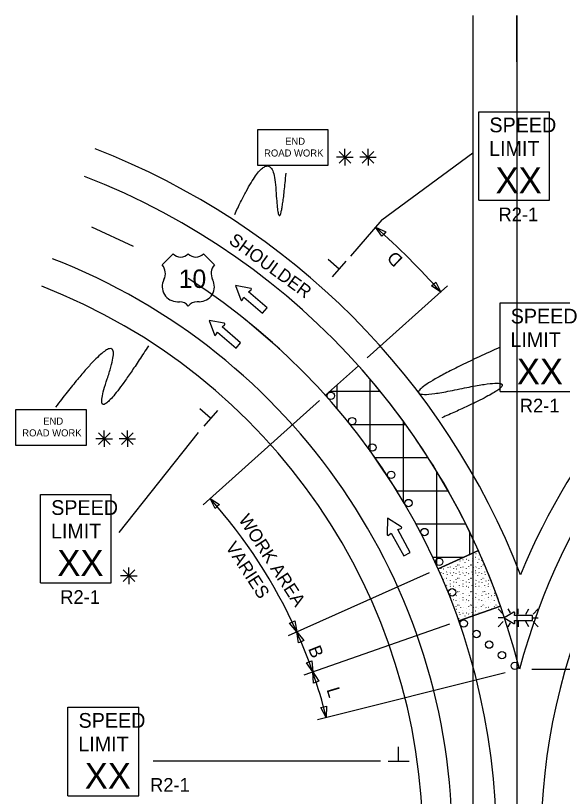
# Model space of a CAD drawing. Extents: x 16556 to 18479, y 5704 to 6974.
# Drawn here: x 16732.7 to 17029.3, y 6550.3 to 6974.1 of the extents above; entities that cross this region are included whole.
import ezdxf

# ---------------------------------------------------------------- set-up
doc = ezdxf.new("R2010")
doc.units = 0
for name, color, linetype in [('ALI_LEGAL_EX', 7, 'Continuous'), ('MT_SCRATCH_LEVEL_A', 7, 'Continuous'), ('MT_SCRATCH_LEVEL_E', 7, 'Continuous'), ('PAVT_EDGE_EX', 7, 'Continuous'), ('TRAFFIC_SIGNS_PR', 7, 'Continuous'), ('TYPICAL_EX', 7, 'Continuous'), ('TYPICAL_TEXT_DIMEN_PR', 7, 'Continuous')]:
    doc.layers.add(name, color=color, linetype=linetype)

msp = doc.modelspace()

# ---------------------------------------------------------------- linework, layer by layer
at = {"layer": 'ALI_LEGAL_EX'}
for p, q in [((16980.68, 6974.12), (16980.68, 6155.98)), ((17004.68, 6974.12), (17004.68, 6155.98)), ((16980.68, 6877.04), (16980.68, 6013.12)), ((17004.68, 6877.04), (17004.68, 6013.12))]:
    msp.add_line(p, q, dxfattribs=at)
for points in [[(17004.68, 6949.12), (17004.68, 6974.12)], [(16796.64, 6848.72), (16773.99, 6859.31)], [(16876.06, 6792.99), (16857.11, 6809.3)], [(16939.89, 6715.82), (16925.99, 6736.59)]]:
    msp.add_lwpolyline(points, dxfattribs=at)
for centre, radius, start, end in [((16629.65, 6525.15), 364, 0, 57.2958), ((17357.65, 6525.15), 340, 129.5666, 180)]:
    msp.add_arc(centre, radius, start, end, dxfattribs=at)
at = {"layer": 'MT_SCRATCH_LEVEL_A'}
for p, q in [((16918.68, 6784), (16900.8, 6767.99)), ((16918.68, 6784), (16900.8, 6767.99)), ((16907.15, 6760.43), (16907.15, 6773.68)), ((16925.15, 6737.43), (16925.15, 6776.33)), ((16903.28, 6770.2), (16930.27, 6770.2)), ((16943.15, 6709.93), (16943.15, 6753.45)), ((16914.07, 6752.2), (16944.07, 6752.2)), ((16927.54, 6734.2), (16956.3, 6734.2)), ((16961.15, 6675.37), (16961.15, 6726.68)), ((16939.35, 6716.2), (16967.15, 6716.2)), ((16949.72, 6698.2), (16976.74, 6698.2)), ((16979.15, 6681.58), (16979.15, 6693.23)), ((16958.82, 6680.2), (16976.08, 6680.2)), ((16983.8, 6683.65), (16961.89, 6673.85)), ((16961.89, 6673.85), (16983.8, 6683.65)), ((16983.8, 6683.65), (16961.89, 6673.85)), ((16978.69, 6681.1), (16978.74, 6681.02)), ((16980.98, 6681.91), (16981.03, 6681.84)), ((16982.43, 6682.06), (16982.48, 6682.18)), ((16984.05, 6681.24), (16984.1, 6681.16)), ((16969.7, 6677.27), (16969.74, 6677.37)), ((16972.49, 6676.04), (16972.54, 6675.96)), ((16973.22, 6676.01), (16973.28, 6675.93)), ((16973.63, 6678.11), (16973.69, 6678.03)), ((16975.41, 6678.78), (16975.47, 6678.89)), ((16976.59, 6677.27), (16976.64, 6677.39)), ((16977.21, 6679.03), (16977.26, 6678.95)), ((16978.49, 6678.45), (16978.5, 6678.33)), ((16979.38, 6676.04), (16979.43, 6675.96)), ((16980.11, 6676.01), (16980.16, 6675.93)), ((16980.33, 6679.31), (16980.38, 6679.42)), ((16980.52, 6678.11), (16980.57, 6678.03)), ((16982.26, 6680.18), (16982.31, 6680.1)), ((16982.3, 6678.78), (16982.35, 6678.89)), ((16983.48, 6677.27), (16983.53, 6677.39)), ((16984.1, 6679.03), (16984.15, 6678.95)), ((16985.38, 6678.45), (16985.39, 6678.33)), ((16986.26, 6676.04), (16986.31, 6675.96)), ((16987, 6676.01), (16987.05, 6675.93)), ((16963.39, 6673.95), (16963.44, 6673.87)), ((16963.44, 6671.74), (16963.49, 6671.66)), ((16964.84, 6675.08), (16964.89, 6675.19)), ((16964.92, 6673.81), (16964.97, 6673.73)), ((16966.56, 6672.02), (16966.61, 6672.14)), ((16967.21, 6674.63), (16967.26, 6674.55)), ((16968.48, 6672.89), (16968.53, 6672.81)), ((16968.65, 6674.78), (16968.71, 6674.9)), ((16970.27, 6673.95), (16970.33, 6673.87)), ((16970.32, 6671.74), (16970.37, 6671.66)), ((16971.72, 6675.08), (16971.78, 6675.19)), ((16971.8, 6673.81), (16971.85, 6673.73)), ((16973.44, 6672.02), (16973.5, 6672.14)), ((16974.09, 6674.63), (16974.15, 6674.55)), ((16975.37, 6672.89), (16975.42, 6672.81)), ((16975.54, 6674.78), (16975.59, 6674.9)), ((16977.16, 6673.95), (16977.21, 6673.87)), ((16977.21, 6671.74), (16977.26, 6671.66)), ((16978.61, 6675.08), (16978.66, 6675.19)), ((16978.69, 6673.81), (16978.74, 6673.73)), ((16980.33, 6672.02), (16980.38, 6672.14)), ((16980.98, 6674.63), (16981.03, 6674.55)), ((16982.26, 6672.89), (16982.31, 6672.81)), ((16982.43, 6674.78), (16982.48, 6674.9)), ((16984.05, 6673.95), (16984.1, 6673.87)), ((16984.1, 6671.74), (16984.15, 6671.66)), ((16985.5, 6675.08), (16985.55, 6675.19)), ((16985.58, 6673.81), (16985.63, 6673.73)), ((16987.22, 6672.02), (16987.27, 6672.14)), ((16964.72, 6671.17), (16964.73, 6671.05)), ((16964.84, 6667.79), (16964.89, 6667.91)), ((16965.6, 6668.75), (16965.65, 6668.68)), ((16966.34, 6668.72), (16966.39, 6668.65)), ((16966.75, 6670.82), (16966.8, 6670.74)), ((16968.53, 6671.49), (16968.58, 6671.61)), ((16968.65, 6667.49), (16968.71, 6667.61)), ((16969.7, 6669.99), (16969.76, 6670.11)), ((16971.6, 6671.17), (16971.62, 6671.05)), ((16971.72, 6667.79), (16971.78, 6667.91)), ((16972.49, 6668.75), (16972.54, 6668.68)), ((16973.22, 6668.72), (16973.28, 6668.65)), ((16973.63, 6670.82), (16973.69, 6670.74)), ((16975.41, 6671.49), (16975.47, 6671.61)), ((16975.54, 6667.49), (16975.59, 6667.61)), ((16976.59, 6669.99), (16976.64, 6670.11)), ((16978.49, 6671.17), (16978.5, 6671.05)), ((16978.61, 6667.79), (16978.66, 6667.91)), ((16979.38, 6668.75), (16979.43, 6668.68)), ((16980.11, 6668.72), (16980.16, 6668.65)), ((16980.52, 6670.82), (16980.57, 6670.74)), ((16982.3, 6671.49), (16982.35, 6671.61)), ((16982.43, 6667.49), (16982.48, 6667.61)), ((16983.48, 6669.99), (16983.53, 6670.11)), ((16985.38, 6671.17), (16985.39, 6671.05)), ((16985.5, 6667.79), (16985.55, 6667.91)), ((16986.26, 6668.75), (16986.31, 6668.68)), ((16987, 6668.72), (16987.05, 6668.65)), ((16987.41, 6670.82), (16987.46, 6670.74)), ((16989.32, 6667.49), (16989.37, 6667.61)), ((16966.56, 6664.74), (16966.61, 6664.85)), ((16966.75, 6663.54), (16966.8, 6663.46)), ((16967.21, 6667.34), (16967.26, 6667.27)), ((16968.48, 6665.61), (16968.53, 6665.53)), ((16968.53, 6664.21), (16968.58, 6664.32)), ((16970.27, 6666.67), (16970.33, 6666.59)), ((16970.32, 6664.46), (16970.37, 6664.38)), ((16971.6, 6663.88), (16971.62, 6663.76)), ((16971.8, 6666.53), (16971.85, 6666.45)), ((16973.44, 6664.74), (16973.5, 6664.85)), ((16973.63, 6663.54), (16973.69, 6663.46)), ((16974.09, 6667.34), (16974.15, 6667.27)), ((16975.37, 6665.61), (16975.42, 6665.53)), ((16975.41, 6664.21), (16975.47, 6664.32)), ((16977.16, 6666.67), (16977.21, 6666.59)), ((16977.21, 6664.46), (16977.26, 6664.38)), ((16978.49, 6663.88), (16978.5, 6663.76)), ((16978.69, 6666.53), (16978.74, 6666.45)), ((16980.33, 6664.74), (16980.38, 6664.85)), ((16980.52, 6663.54), (16980.57, 6663.46)), ((16980.98, 6667.34), (16981.03, 6667.27)), ((16982.26, 6665.61), (16982.31, 6665.53)), ((16982.3, 6664.21), (16982.35, 6664.32)), ((16984.05, 6666.67), (16984.1, 6666.59)), ((16984.1, 6664.46), (16984.15, 6664.38)), ((16985.38, 6663.88), (16985.39, 6663.76)), ((16985.58, 6666.53), (16985.63, 6666.45)), ((16987.22, 6664.74), (16987.27, 6664.85)), ((16987.41, 6663.54), (16987.46, 6663.46)), ((16987.87, 6667.34), (16987.92, 6667.27)), ((16989.15, 6665.61), (16989.2, 6665.53)), ((16989.19, 6664.21), (16989.24, 6664.32)), ((16990.99, 6664.46), (16991.04, 6664.38)), ((16968.65, 6660.21), (16968.71, 6660.33)), ((16969.7, 6662.7), (16969.76, 6662.82)), ((16970.27, 6659.38), (16970.33, 6659.3)), ((16971.72, 6660.51), (16971.78, 6660.62)), ((16971.8, 6659.24), (16971.85, 6659.16)), ((16972.49, 6661.47), (16972.54, 6661.39)), ((16973.22, 6661.44), (16973.28, 6661.36)), ((16974.09, 6660.06), (16974.15, 6659.98)), ((16975.54, 6660.21), (16975.59, 6660.33)), ((16976.59, 6662.7), (16976.64, 6662.82)), ((16977.16, 6659.38), (16977.21, 6659.3)), ((16978.61, 6660.51), (16978.66, 6660.62)), ((16978.69, 6659.24), (16978.74, 6659.16)), ((16979.38, 6661.47), (16979.43, 6661.39)), ((16980.11, 6661.44), (16980.16, 6661.36)), ((16980.98, 6660.06), (16981.03, 6659.98)), ((16982.43, 6660.21), (16982.48, 6660.33)), ((16983.48, 6662.7), (16983.53, 6662.82)), ((16984.05, 6659.38), (16984.1, 6659.3)), ((16985.5, 6660.51), (16985.55, 6660.62)), ((16985.58, 6659.24), (16985.63, 6659.16)), ((16986.26, 6661.47), (16986.31, 6661.39)), ((16987, 6661.44), (16987.05, 6661.36)), ((16987.87, 6660.06), (16987.92, 6659.98)), ((16989.32, 6660.21), (16989.37, 6660.33)), ((16990.37, 6662.7), (16990.42, 6662.82)), ((16990.94, 6659.38), (16990.99, 6659.3)), ((16992.39, 6660.51), (16992.44, 6660.62)), ((16992.47, 6659.24), (16992.52, 6659.16)), ((16968.48, 6658.32), (16968.53, 6658.24)), ((16969.7, 6655.42), (16969.76, 6655.54)), ((16970.32, 6657.17), (16970.37, 6657.09)), ((16971.6, 6656.6), (16971.62, 6656.48)), ((16973.44, 6657.45), (16973.5, 6657.57)), ((16973.63, 6656.25), (16973.69, 6656.18)), ((16975.37, 6658.32), (16975.42, 6658.24)), ((16975.41, 6656.92), (16975.47, 6657.04)), ((16976.59, 6655.42), (16976.64, 6655.54)), ((16977.21, 6657.17), (16977.26, 6657.09)), ((16978.49, 6656.6), (16978.5, 6656.48)), ((16980.33, 6657.45), (16980.38, 6657.57)), ((16980.52, 6656.25), (16980.57, 6656.18)), ((16982.26, 6658.32), (16982.31, 6658.24)), ((16982.3, 6656.92), (16982.35, 6657.04)), ((16983.48, 6655.42), (16983.53, 6655.54)), ((16984.1, 6657.17), (16984.15, 6657.09)), ((16985.38, 6656.6), (16985.39, 6656.48)), ((16987.22, 6657.45), (16987.27, 6657.57)), ((16987.41, 6656.25), (16987.46, 6656.18)), ((16989.15, 6658.32), (16989.2, 6658.24)), ((16989.19, 6656.92), (16989.24, 6657.04)), ((16990.37, 6655.42), (16990.42, 6655.54)), ((16990.99, 6657.17), (16991.04, 6657.09)), ((16992.27, 6656.6), (16992.28, 6656.48)), ((16994.11, 6657.45), (16994.16, 6657.57)), ((16994.3, 6656.25), (16994.35, 6656.18)), ((16971.72, 6653.22), (16971.78, 6653.34)), ((16971.8, 6651.96), (16971.85, 6651.88)), ((16972.49, 6654.18), (16972.54, 6654.11)), ((16995.8, 6653.51), (16973.15, 6645.57)), ((16973.15, 6645.57), (16995.8, 6653.51)), ((16973.22, 6654.15), (16973.28, 6654.07)), ((16974.09, 6652.77), (16974.15, 6652.7)), ((16975.37, 6651.04), (16975.42, 6650.96)), ((16975.54, 6652.93), (16975.59, 6653.04)), ((16977.16, 6652.1), (16977.21, 6652.02)), ((16978.61, 6653.22), (16978.66, 6653.34)), ((16978.69, 6651.96), (16978.74, 6651.88)), ((16979.38, 6654.18), (16979.43, 6654.11)), ((16980.11, 6654.15), (16980.16, 6654.07)), ((16980.98, 6652.77), (16981.03, 6652.7)), ((16982.26, 6651.04), (16982.31, 6650.96)), ((16982.43, 6652.93), (16982.48, 6653.04)), ((16984.05, 6652.1), (16984.1, 6652.02)), ((16985.5, 6653.22), (16985.55, 6653.34)), ((16985.58, 6651.96), (16985.63, 6651.88)), ((16986.26, 6654.18), (16986.31, 6654.11)), ((16987, 6654.15), (16987.05, 6654.07)), ((16987.87, 6652.77), (16987.92, 6652.7)), ((16989.32, 6652.93), (16989.37, 6653.04)), ((16990.94, 6652.1), (16990.99, 6652.02)), ((16992.39, 6653.22), (16992.44, 6653.34)), ((16993.15, 6654.18), (16993.2, 6654.11)), ((16993.89, 6654.15), (16993.94, 6654.07)), ((16973.22, 6646.87), (16973.28, 6646.79)), ((16973.44, 6650.17), (16973.5, 6650.28)), ((16973.63, 6648.97), (16973.69, 6648.89)), ((16975.41, 6649.64), (16975.47, 6649.75)), ((16976.59, 6648.13), (16976.64, 6648.25)), ((16977.21, 6649.89), (16977.26, 6649.81)), ((16978.49, 6649.31), (16978.5, 6649.19)), ((16980.33, 6650.17), (16980.38, 6650.28)), ((16980.52, 6648.97), (16980.57, 6648.89)), ((16982.3, 6649.64), (16982.35, 6649.75)), ((16984.1, 6649.89), (16984.15, 6649.81))]:
    msp.add_line(p, q, dxfattribs=at)
for start, end in [(24.1122, 41.8471), (19.3199, 24.1122)]:
    msp.add_arc((16629.65, 6525.15), 388, start, end, dxfattribs=at)
at = {"layer": 'MT_SCRATCH_LEVEL_E'}
for p, q in [((16860.24, 6826.04), (16852.05, 6827.62)), ((16852.05, 6827.62), (16854.86, 6819.78)), ((16859.05, 6824.09), (16860.45, 6825.23)), ((16855.69, 6819.7), (16856.61, 6821.26)), ((16856.61, 6821.26), (16866.66, 6812.61)), ((16869.1, 6815.45), (16859.05, 6824.09)), ((16866.66, 6812.61), (16869.1, 6815.45)), ((16845.92, 6807.1), (16837.72, 6808.67)), ((16837.72, 6808.67), (16840.53, 6800.84)), ((16844.72, 6805.15), (16846.12, 6806.29)), ((16854.77, 6796.5), (16844.72, 6805.15)), ((16841.36, 6800.76), (16842.28, 6802.31)), ((16842.28, 6802.31), (16852.33, 6793.66)), ((16852.33, 6793.66), (16854.77, 6796.5))]:
    msp.add_line(p, q, dxfattribs=at)
for centre, start, end in [((16860.15, 6825.59), 309.3361, 79.073), ((16855.3, 6819.95), 199.7248, 329.2637), ((16845.82, 6806.64), 309.3361, 79.073), ((16840.97, 6801), 199.7248, 329.2637)]:
    msp.add_arc(centre, 0.463, start, end, dxfattribs=at)
at = {"layer": 'PAVT_EDGE_EX'}
for centre, radius, start, end in [((16629.65, 6525.15), 404, 21.0961, 68.7791), ((16629.65, 6525.15), 388, 14.0482, 68.7791), ((16629.65, 6525.15), 340, 0, 68.7791), ((17357.65, 6525.15), 380, 123.6935, 157.5011), ((16629.65, 6525.15), 324, 0, 68.7791), ((17357.65, 6525.15), 364, 123.6935, 165.0045)]:
    msp.add_arc(centre, radius, start, end, dxfattribs=at)
at = {"layer": 'TRAFFIC_SIGNS_PR'}
for p, q in [((16983.99, 6921.9), (17022.39, 6921.9)), ((16983.99, 6873.9), (16983.99, 6921.9)), ((17022.39, 6873.9), (17022.39, 6921.9)), ((16983.99, 6873.9), (17022.39, 6873.9)), ((16995.55, 6818.12), (17033.95, 6818.12)), ((16995.55, 6770.12), (16995.55, 6818.12)), ((16995.55, 6770.12), (17033.95, 6770.12)), ((16746.24, 6714.2), (16784.64, 6714.2)), ((16746.24, 6666.2), (16746.24, 6714.2)), ((16784.64, 6666.2), (16784.64, 6714.2)), ((16746.24, 6666.2), (16784.64, 6666.2)), ((16994.48, 6652.01), (16997.3, 6649.19)), ((17001.2, 6649.83), (16999.94, 6652.01)), ((17005.38, 6649.19), (17005.38, 6652.01)), ((17009.51, 6649.19), (17011.14, 6652.01)), ((17013.47, 6649.19), (17016.29, 6652.02)), ((16997.3, 6647.16), (16994.48, 6647.16)), ((17013.47, 6647.16), (17016.29, 6647.16)), ((16994.48, 6642.31), (16997.3, 6645.13)), ((16999.91, 6642.31), (17001.12, 6644.4)), ((17005.38, 6645.13), (17005.38, 6642.31)), ((17011.17, 6642.31), (17009.54, 6645.13)), ((17013.47, 6645.13), (17016.29, 6642.31)), ((16761.11, 6598.64), (16799.51, 6598.64)), ((16761.11, 6550.64), (16761.11, 6598.64)), ((16799.51, 6550.64), (16799.51, 6598.64)), ((16761.11, 6550.64), (16799.51, 6550.64))]:
    msp.add_line(p, q, dxfattribs=at)
for points in [[(16863.93, 6892.88), (16902.33, 6892.88), (16902.33, 6912.08), (16863.93, 6912.08)], [(16732.72, 6740.93), (16771.12, 6740.93), (16771.12, 6760.13), (16732.72, 6760.13)]]:
    msp.add_lwpolyline(points, close=True, dxfattribs=at)
for points in [[(17003.05, 6650.18), (16997.74, 6647.16), (17003.05, 6644.12)], [(17003.55, 6644.48), (17003.32, 6645.78), (17013.05, 6645.78), (17013.05, 6648.52), (17003.32, 6648.52), (17003.56, 6649.82)]]:
    msp.add_lwpolyline(points, dxfattribs=at)
for centre in [(16903.73, 6767.76), (16915.33, 6753.99), (16926.23, 6739.67), (16936.42, 6724.84), (16945.86, 6709.51), (16954.54, 6693.75), (16962.44, 6677.57), (16969.53, 6661.03), (16975.8, 6644.16), (16982.72, 6638.4), (16989.65, 6632.65), (16996.57, 6626.9), (17003.5, 6621.15)]:
    msp.add_circle(centre, 2, dxfattribs=at)
for centre, start, end in [((17003.22, 6649.88), 350.7308, 118.8916), ((17003.22, 6644.42), 241.4833, 9.9593)]:
    msp.add_arc(centre, 0.341, start, end, dxfattribs=at)
at = {"layer": 'TYPICAL_EX'}
for p, q in [((16812.25, 6838.84), (16818.14, 6844.74)), ((16840.55, 6838.84), (16834.65, 6844.74)), ((16820.49, 6818.78), (16821.67, 6818.78)), ((16832.3, 6818.78), (16831.12, 6818.78))]:
    msp.add_line(p, q, dxfattribs=at)
for centre, radius, start, end in [((16822.27, 6849.03), 5.96, 226.1404, 313.8596), ((16830.52, 6849.03), 5.96, 226.1404, 313.8596), ((16806.66, 6834.12), 7.31, 333.0977, 40.1936), ((16846.13, 6834.12), 7.31, 139.8064, 206.9023), ((16820.51, 6827.03), 8.24, 152.6698, 269.9013), ((16832.29, 6827.03), 8.24, 270.0987, 27.3302), ((16821.69, 6812.88), 5.91, 37.1038, 90.1385), ((16831.11, 6812.88), 5.91, 89.8615, 142.8962)]:
    msp.add_arc(centre, radius, start, end, dxfattribs=at)
at = {"layer": 'TYPICAL_TEXT_DIMEN_PR'}
for p, q in [((16911.35, 6897.25), (16911.35, 6901.71)), ((16923.9, 6897.25), (16923.9, 6901.71)), ((16911.35, 6897.25), (16906.82, 6897.25)), ((16908.16, 6900.44), (16914.54, 6894.06)), ((16914.54, 6900.44), (16908.16, 6894.06)), ((16911.35, 6897.25), (16914.54, 6897.25)), ((16911.35, 6897.25), (16915.83, 6897.25)), ((16911.35, 6897.25), (16911.35, 6892.75)), ((16923.9, 6897.25), (16919.37, 6897.25)), ((16920.72, 6900.44), (16927.09, 6894.06)), ((16927.09, 6900.44), (16920.72, 6894.06)), ((16923.9, 6897.25), (16927.09, 6897.25)), ((16923.9, 6897.25), (16928.38, 6897.25)), ((16923.9, 6897.25), (16923.9, 6892.75)), ((16931.32, 6863.17), (16980.76, 6899.6)), ((16931.32, 6863.17), (16914.34, 6843.48)), ((16931.42, 6854.32), (16928.01, 6859.34)), ((16928.01, 6859.34), (16933.48, 6856.7)), ((16932.45, 6855.51), (16931.42, 6854.32)), ((16933.48, 6856.7), (16932.45, 6855.51)), ((16908.16, 6836.56), (16902.26, 6841.65)), ((16911.83, 6840.82), (16904.48, 6832.31)), ((16959.47, 6828.39), (16960.64, 6829.44)), ((16960.64, 6829.44), (16963.38, 6824.03)), ((16967.1, 6827.36), (16923.44, 6788.26)), ((16958.3, 6827.35), (16959.47, 6828.39)), ((16963.38, 6824.03), (16958.3, 6827.35)), ((16897.57, 6765.1), (16834.51, 6708.61)), ((16838.5, 6755.55), (16832.6, 6760.63)), ((16842.17, 6759.8), (16834.82, 6751.29)), ((16780.79, 6744.43), (16780.79, 6748.88)), ((16793.34, 6744.43), (16793.34, 6748.88)), ((16780.79, 6744.43), (16776.26, 6744.43)), ((16777.6, 6747.62), (16783.97, 6741.24)), ((16783.97, 6747.62), (16777.6, 6741.24)), ((16780.79, 6744.43), (16783.97, 6744.43)), ((16780.79, 6744.43), (16785.26, 6744.43)), ((16780.79, 6744.43), (16780.79, 6739.93)), ((16831.74, 6747.71), (16788.67, 6693.51)), ((16793.34, 6744.43), (16788.81, 6744.43)), ((16796.53, 6747.62), (16790.15, 6741.24)), ((16790.16, 6747.62), (16796.53, 6741.24)), ((16793.34, 6744.43), (16796.53, 6744.43)), ((16793.34, 6744.43), (16797.82, 6744.43)), ((16793.34, 6744.43), (16793.34, 6739.93)), ((16840.97, 6706.53), (16838.23, 6711.95)), ((16838.23, 6711.95), (16843.31, 6708.63)), ((16842.14, 6707.58), (16840.97, 6706.53)), ((16843.31, 6708.63), (16842.14, 6707.58)), ((16934.39, 6701.31), (16934.23, 6692.43)), ((16941.97, 6696.64), (16934.39, 6701.31)), ((16935.03, 6692.03), (16936.54, 6693.23)), ((16936.54, 6693.23), (16943.3, 6680.81)), ((16940.04, 6695.14), (16941.87, 6695.75)), ((16946.8, 6682.72), (16940.04, 6695.14)), ((16943.3, 6680.81), (16946.8, 6682.72)), ((16791.02, 6673.24), (16797.39, 6666.86)), ((16797.39, 6673.24), (16791.02, 6666.86)), ((16794.2, 6670.05), (16794.2, 6674.5)), ((16794.2, 6670.05), (16789.67, 6670.05)), ((16794.2, 6670.05), (16797.39, 6670.05)), ((16794.2, 6670.05), (16798.68, 6670.05)), ((16794.2, 6670.05), (16794.2, 6665.55)), ((16957.06, 6671.69), (16880.65, 6637.49)), ((16881.39, 6644.24), (16882.82, 6644.88)), ((16885.22, 6639.53), (16881.39, 6644.24)), ((16882.82, 6644.88), (16884.26, 6645.53)), ((16884.26, 6645.53), (16885.22, 6639.53)), ((16968.07, 6643.79), (16889.16, 6616.13)), ((16886.18, 6633.54), (16885.22, 6639.53)), ((16885.22, 6639.53), (16889.05, 6634.82)), ((16887.61, 6634.18), (16886.18, 6633.54)), ((16889.05, 6634.82), (16887.61, 6634.18)), ((16890.46, 6622.79), (16891.94, 6623.31)), ((16893.88, 6617.78), (16890.46, 6622.79)), ((16891.94, 6623.31), (16893.42, 6623.83)), ((16893.42, 6623.83), (16893.88, 6617.78)), ((16894.34, 6611.73), (16893.88, 6617.78)), ((16893.88, 6617.78), (16897.3, 6612.77)), ((16998.34, 6617.4), (16896.42, 6591.9)), ((17012.72, 6619.33), (17106.65, 6619.33)), ((16897.3, 6612.77), (16895.82, 6612.25)), ((16895.82, 6612.25), (16894.34, 6611.73)), ((16898.33, 6598.42), (16899.85, 6598.8)), ((16901.28, 6593.11), (16898.33, 6598.42)), ((16899.85, 6598.8), (16901.38, 6599.18)), ((16901.38, 6599.18), (16901.28, 6593.11)), ((16940.52, 6569.33), (16940.52, 6577.11)), ((16930.65, 6569.33), (16807.28, 6569.33)), ((16934.9, 6569.33), (16946.15, 6569.33))]:
    msp.add_line(p, q, dxfattribs=at)
for centre, radius, start, end in [((16629.65, 6525.15), 448, 41.8471, 48.2417), ((16629.65, 6525.15), 280, 24.1124, 41.8469), ((16941.7, 6696.22), 0.494, 288.5864, 58.3233), ((16934.73, 6692.42), 0.494, 178.9751, 308.514), ((16629.65, 6525.15), 280, 19.32, 24.1124), ((16629.65, 6525.15), 280, 14.0482, 19.32)]:
    msp.add_arc(centre, radius, start, end, dxfattribs=at)
for points in [[(16851.6, 6866.22), (16872.23, 6911.03), (16875.68, 6847.69), (16879.45, 6888.56)], [(16804.77, 6794.84), (16770.22, 6740.99), (16795.41, 6815.31), (16754.41, 6761.64)], [(16995.55, 6794.12), (16920.47, 6760.07), (17024.9, 6782.44), (16963.88, 6755.75)]]:
    msp.add_open_spline(points, degree=2, dxfattribs=at)

# ---------------------------------------------------------------- texts
at = {"layer": 'TRAFFIC_SIGNS_PR'}
for s, height, p in [('SPEED', 8, (16989.76, 6910.77)), ('END', 3.831, (16878.93, 6904.01)), ('LIMIT', 8, (16989.59, 6897.97)), ('ROAD WORK', 3.831, (16867.53, 6897.62)), ('XX', 14.031, (16993.1, 6877.66)), ('R2-1', 7.44, (16994.67, 6862.46)), ('SPEED', 8, (17001.31, 6806.98)), ('LIMIT', 8, (17001.15, 6794.18)), ('XX', 14.031, (17004.66, 6773.88)), ('R2-1', 7.44, (17006.22, 6758.68)), ('END', 3.831, (16747.72, 6752.06)), ('ROAD WORK', 3.831, (16736.33, 6745.67)), ('SPEED', 8, (16752.01, 6703.06)), ('LIMIT', 8, (16751.85, 6690.26)), ('XX', 14.031, (16755.36, 6669.95)), ('R2-1', 7.44, (16756.92, 6654.76)), ('SPEED', 8, (16766.87, 6587.5)), ('LIMIT', 8, (16766.71, 6574.7)), ('XX', 14.031, (16770.22, 6554.4)), ('R2-1', 7.44, (16805.63, 6552.77))]:
    msp.add_text(s, height=height, dxfattribs=at).set_placement(p)
at = {"layer": 'TYPICAL_EX'}
msp.add_text('10', height=10, dxfattribs=at).set_placement((16821.24, 6826.27))
at = {"layer": 'TYPICAL_TEXT_DIMEN_PR'}
for s, rotation, p in [('SHOULDER', 323.9582, (16847.89, 6850.87)), ('D', 135.5356, (16943.28, 6842.1)), ('WORK AREA', 302.9795, (16853.38, 6700.56)), ('VARIES', 302.9795, (16846.34, 6685.69)), ('B', 291.7155, (16891.28, 6630.46)), ('L', 286.685, (16901.34, 6608.32))]:
    msp.add_text(s, height=7, rotation=rotation, dxfattribs=at).set_placement(p)

doc.saveas('drawing.dxf')
